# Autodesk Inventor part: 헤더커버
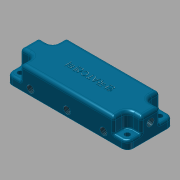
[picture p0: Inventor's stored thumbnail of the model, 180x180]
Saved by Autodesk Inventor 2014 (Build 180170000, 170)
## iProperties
Created: 2015-11
Part Number: 헤더커버
Material: 알루미늄 6061
Document SubType Name: Modeling
Designer: mduedu
Density: 2.71 g/cm^3
Appearance: 하늘색 짙음
Mass: 171.771 g
Surface Area: 160.862 cm^2
Volume: 63.3841 cm^3
Author: mduedu
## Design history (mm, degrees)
sketch "스케치1"
  geometry: L1 (52.5, 20)-(-52.5, 20); L2 (-52.5, 20)-(-52.5, -20); L3 (-52.5, -20)-(52.5, -20); L4 (52.5, -20)-(52.5, 20); L5 (52.5, 20)-(-52.5, -20); L6 (-52.5, 20)-(52.5, -20); 1 further point
  constraints: 12 end point, 2 midpoint, 2 parallel, 1 horizontal, 1 perpendicular
  dimensions: "d0" = 105 distance of L3.end L2.end; "d1" = 40 distance of L2.end L1.end
extrude "돌출1" new body sketch "스케치1" distance "d2" = 20; taper "d3" = 0 deg
sketch "스케치2"
  geometry: L1 (-52.5, -20)-(-52.5, 20) reference; L2 (-52.5, 20)-(52.5, 20) reference; L3 (52.5, 20)-(52.5, -20) reference; L4 (52.5, -20)-(-52.5, -20) reference; L5 (-52.5, 20)-(-40.5, 20); L6 (-40.5, 20)-(-40.5, 8); L7 (-40.5, 8)-(-52.5, 8); L8 (-52.5, 8)-(-52.5, 20); L9 (52.5, 20)-(40.5, 20); L10 (40.5, 20)-(40.5, 8); L11 (40.5, 8)-(52.5, 8); L12 (52.5, 8)-(52.5, 20); L13 (52.5, -20)-(40.5, -20); L14 (40.5, -20)-(40.5, -8); L15 (40.5, -8)-(52.5, -8); L16 (52.5, -8)-(52.5, -20); L17 (-52.5, -20)-(-40.5, -20); L18 (-40.5, -20)-(-40.5, -8); L19 (-40.5, -8)-(-52.5, -8); L20 (-52.5, -8)-(-52.5, -20); 1 further point
  constraints: 32 end point, 8 parallel, 6 equal length, 4 horizontal, 4 perpendicular
  dimensions: "d4" = 12 distance of L6.end L7.end; "d5" = 12 distance of L5.end L6.end
extrude "돌출2" cut sketch "스케치2" distance "d6" = 13; taper "d7" = 0 deg
fillet "모깎기1" dims "d8" = 5
fillet "모깎기2" dims "d9" = 1
fillet "모깎기3" dims "d10" = 5
fillet "모깎기4" dims "d11" = 2
fillet "모깎기5" dims "d12" = 3
sketch "스케치3"
  geometry: L1 (-46.5, -14)-(46.5, -14); L2 (46.5, -14)-(46.5, 14); L3 (46.5, 14)-(-46.5, 14); L4 (-46.5, 14)-(-46.5, -14); L5 (-46.5, -14)-(46.5, 14); L6 (46.5, -14)-(-46.5, 14); L7 (47.5, 20)-(-47.5, 20) reference; L8 (52.5, -15)-(52.5, 15) reference; 5 further points
  constraints: 12 end point, 4 coincident, 2 midpoint, 2 parallel, 1 horizontal, 1 perpendicular
  dimensions: "d13" = 6 distance between parallel lines of L3 L7; "d14" = 6 distance between parallel lines of L2 L8
hole "구멍1" sketch "스케치3" at (-46.5, 14), (46.5, 14), (46.5, -14), (-46.5, -14) diameter "d15" = 4.5; stored, may be unused: countersink angle "d19" = 90 deg, drill point angle "d21" = 118 deg; dims "d16" = 6, "d17" = 4, "d18" = 2, "d20" = 8
sketch "스케치4"
  geometry: L1 (47.5, -20)-(-47.5, -20) reference; L2 (52.5, 15)-(52.5, -15) reference; L3 (-47.5, 20)-(47.5, 20) reference; L4 (-52.5, -15)-(-52.5, 15) reference; L5 (-52.5, 0)-(52.5, 0); C1 r 12.25 at (0, 0); C2 r 2.25 at (46.5, 14) reference; C3 r 2.25 at (-46.5, -14) reference; C4 r 2.25 at (46.5, -14) reference; C5 r 2.25 at (-46.5, 14) reference; C6 r 12.25 at (-32, 0); C7 r 12.25 at (32, 0); A1 r 5 centre (-47.5, -15) between (-52.5, -15) and (-47.5, -20) reference; A2 r 5 centre (47.5, -15) between (47.5, -20) and (52.5, -15) reference; A3 r 5 centre (47.5, 15) between (52.5, 15) and (47.5, 20) reference; A4 r 5 centre (-47.5, 15) between (-47.5, 20) and (-52.5, 15) reference; 1 further point
  constraints: 3 centre point, 2 end point, 2 midpoint, 2 point on line, 1 coincident
  dimensions: "d22" = 24.5 diameter of C1; "d23" = 24.5 diameter of C7 (= d22); "d24" = 24.5 diameter of C6 (= d22); "d25" = 32 distance of point (0, 0) C6.centre; "d26" = 32 distance of C7.centre point (0, 0) (= d25)
extrude "돌출3" cut sketch "스케치4" distance "d27" = 8; taper "d28" = 0 deg
fillet "모깎기6" dims "d29" = 5
sketch "스케치5"
  geometry: L1 (-52.5, 12)-(-47.119, 12); L2 (-40.191, 8)-(-37.635, 3.574); L3 (-52.5, 17)-(-52.5, 8) reference; L4 (-47.5, 0)-(-52.5, 0) reference; L5 (37.5, 20)-(-37.5, 20) reference; L6 (0, 0)-(0, 20); L7 (52.5, 12)-(47.119, 12); L8 (40.191, 8)-(37.635, 3.574); A1 r 8 centre (-47.119, 4) between (-40.191, 8) and (-47.119, 12); A2 r 8 centre (47.119, 4) between (47.119, 12) and (40.191, 8); 1 further point
  constraints: 10 end point, 5 symmetric about line, 4 point on circle, 3 point on line, 2 centre point, 2 tangent, 1 horizontal, 1 midpoint, 1 other
  dimensions: "d30" = 10 distance of L1.start point (-42.5, 12); "d32" = 120 deg angle of L2 L1; "d34" = 12 distance between parallel lines of L1 L4; "d35" = 8 radius of A1
sketch "스케치6"
  geometry: L1 (20, -5)-(20, 5) reference; L2 (8, -20)-(17, -20) reference; L3 (12, -20)-(12, -14.619); L4 (8, -7.691)-(3.81, -5.272); L5 (0, -20)-(0, -15) reference; A1 r 8 centre (4, -14.619) between (12, -14.619) and (8, -7.691); 2 further points
  constraints: 4 end point, 3 point on line, 2 point on circle, 2 tangent, 1 centre point, 1 perpendicular
  dimensions: "d36" = 10 distance of L3.start point (12, -10); "d38" = 12 distance between parallel lines of L3 L5; "d39" = 120 deg angle of L3 L4; "d40" = 8 radius of A1
node "작업점1"
node "작업점2"
node "작업점3"
hole "구멍2" diameter "d43" = 5.944; stored, may be unused: countersink angle "d49" = 90 deg, drill point angle "d51" = 0 deg; dims "d41" = 10, "d42" = 10, "d44" = 6.886, "d45" = 0.62479, "d46" = 5.959, "d47" = 4, "d48" = 2, "d50" = 6.9
hole "구멍3" diameter "d54" = 5.944; stored, may be unused: countersink angle "d60" = 90 deg, drill point angle "d62" = 0 deg; dims "d52" = 10, "d53" = 10, "d55" = 6.886, "d56" = 0.62479, "d57" = 5.959, "d58" = 4, "d59" = 2, "d61" = 6.9
hole "구멍4" diameter "d65" = 5.944; stored, may be unused: countersink angle "d71" = 90 deg, drill point angle "d73" = 0 deg; dims "d63" = 10, "d64" = 10, "d66" = 6.886, "d67" = 0.62479, "d68" = 5.959, "d69" = 4, "d70" = 2, "d72" = 6.9
sketch "스케치7"
  geometry: C1 r 2.972 at (15, 12) reference; 1 further point
sketch "스케치8"
  geometry: C1 r 2.972 at (15, 12) reference; 1 further point
sketch "스케치9"
  geometry: C1 r 2.972 at (47.5, 12) reference; 1 further point
feature "스윕1" dims "d74" = 0
feature "스윕2" dims "d75" = 0
feature "스윕3" dims "d76" = 0
sketch "스케치10"
  geometry: L1 (0, 0)-(95, 0) reference; L2 (22.75, 8)-(8.768, 8) reference; L3 (54.75, 8)-(40.25, 8) reference; L4 (86.232, 8)-(72.25, 8) reference; L5 (15.759, 8)-(15.759, 0); L6 (47.5, 8)-(47.5, 0); L7 (79.241, 8)-(79.241, 0); 5 further points
  constraints: 6 end point, 5 point on line, 3 midpoint, 2 horizontal alignment, 2 perpendicular, 1 parallel
  dimensions: "d77" = 5 distance from line of point (15.759, 5) L1
hole "구멍5" sketch "스케치10" at (15.759, 5), (47.5, 5), (79.241, 5) diameter "d78" = 5.944; stored, may be unused: countersink angle "d84" = 90 deg, drill point angle "d86" = 0 deg; dims "d79" = 6.886, "d80" = 0.62479, "d81" = 5.959, "d82" = 4, "d83" = 2, "d85" = 6.9
sketch "스케치11"
  geometry: C1 r 2.972 at (0, 0) reference; C2 r 2.972 at (31.741, 0) reference; C3 r 2.972 at (63.482, 0) reference; 1 further point
extrude "돌출4" cut sketch "스케치11" distance "d87" = 8; taper "d88" = 0 deg
sketch "스케치12"
  geometry: 2 further points
  constraints: 1 coincident, 1 other
feature "엠보싱1" sketch "스케치12" dims "d0" = 105, "d1" = 40, "d4" = 12, "d5" = 12, "d89" = 0.5, "d90" = 0
node "솔리드1"
node "투영된 루프1"
node "절단 모서리 투영1"
